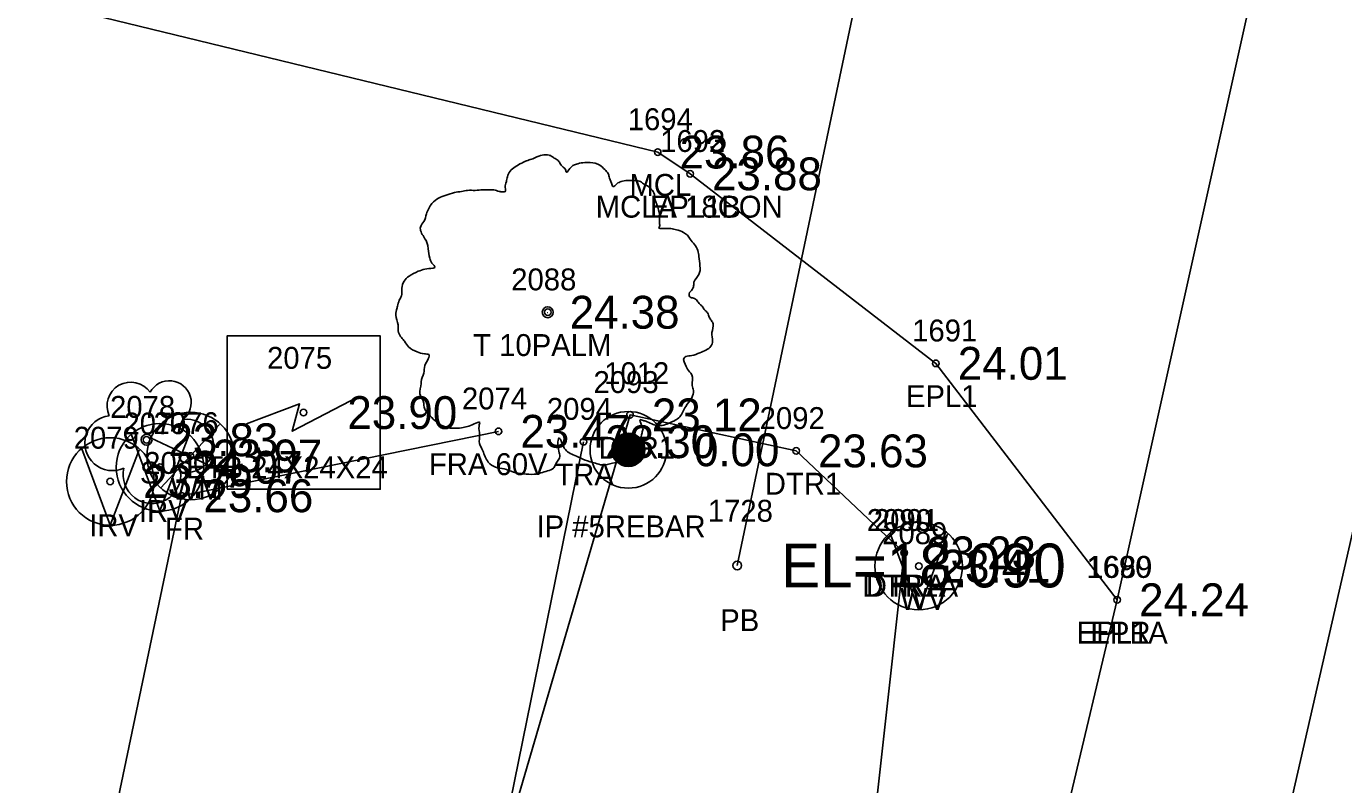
# Model space of a CAD drawing. Extents: x 2654414 to 2656963, y 761776 to 764965.
# Drawn here: x 2655410.2 to 2655470.4, y 762159.7 to 762194.4 of the extents above; entities that cross this region are included whole.
import ezdxf

# ---------------------------------------------------------------- set-up
doc = ezdxf.new("R2010")
doc.units = 0
for name, color, linetype in [('Default', 7, 'Continuous'), ('RD_EX_BldgApp', 7, 'Continuous'), ('RD_EX_Conc', 7, 'Continuous'), ('RD_EX_Conc_txCode', 7, 'Continuous'), ('RD_EX_DR_Pipe', 7, 'Continuous'), ('RD_EX_DR_Pipe_txCode', 7, 'Continuous'), ('RD_EX_DV_Prop_txCode', 7, 'Continuous'), ('RD_EX_DV_PropPin', 7, 'Continuous'), ('RD_EX_Fence_Other', 7, 'Continuous'), ('RD_EX_Fence_Other_txCode', 7, 'Continuous'), ('RD_EX_H2O', 7, 'Continuous'), ('RD_EX_H2O_txCode', 7, 'Continuous'), ('RD_EX_Misc_txCode', 7, 'Continuous'), ('RD_EX_Road', 7, 'Continuous'), ('RD_EX_Road_txCode', 7, 'Continuous'), ('RD_EX_TX_Conc_ELEV', 7, 'Continuous'), ('RD_EX_TX_DV_Prop_ELEV', 7, 'Continuous'), ('RD_EX_TX_Fence_Other_ELEV', 7, 'Continuous'), ('RD_EX_TX_H2O_ELEV', 7, 'Continuous'), ('RD_EX_TX_Misc_ELEV', 7, 'Continuous'), ('RD_EX_TX_Road_ELEV', 7, 'Continuous'), ('RD_EX_TX_UT_ELEV', 7, 'Continuous'), ('RD_EX_TX_VEG_ELEV', 7, 'Continuous'), ('RD_EX_UT', 7, 'Continuous'), ('RD_EX_UT_txCode', 7, 'Continuous'), ('RD_EX_VEG', 7, 'Continuous'), ('RD_EX_VEG_txCode', 7, 'Continuous'), ('RD_HC_Cl', 7, 'Continuous'), ('RD_SMD_Locator', 7, 'Continuous'), ('RD_TX_Pipe_ElevEX', 7, 'Continuous')]:
    doc.layers.add(name, color=color, linetype=linetype)

msp = doc.modelspace()

# ---------------------------------------------------------------- linework, layer by layer
at = {"layer": 'Default'}
msp.add_line((2656050.51, 764712.367), (2655383.263, 761787.511), dxfattribs=at)
at = {"layer": 'RD_EX_BldgApp'}
for p, q in [((2655416.316, 762172.224), (2655415.012, 762175.707)), ((2655416.316, 762172.224), (2655417.638, 762175.669)), ((2655414.044, 762171.575), (2655412.74, 762175.057)), ((2655414.044, 762171.575), (2655415.366, 762175.02))]:
    msp.add_line(p, q, dxfattribs=at)
for centre, radius in [((2655416.316, 762174.217), 2), ((2655414.044, 762173.567), 2), ((2655416.316, 762174.217), 0.15), ((2655414.044, 762173.567), 0.15)]:
    msp.add_circle(centre, radius, dxfattribs=at)
at = {"layer": 'RD_EX_Conc'}
msp.add_lwpolyline([(2655440.54, 762187.622), (2655439.059, 762188.617), (2655385.758, 762201.571), (2655364.155, 762208.612), (2655337.932, 762214.524), (2655306.963, 762222.49), (2655288.125, 762231.245)], dxfattribs=at)
at = {"layer": 'RD_EX_DR_Pipe'}
msp.add_line((2655454.649, 762226.686), (2655442.695, 762169.731), dxfattribs=at)
at = {"layer": 'RD_EX_DV_PropPin'}
for p, q in [((2655437.015, 762174.717), (2655437.015, 762175.313)), ((2655437.051, 762174.645), (2655437.051, 762175.384)), ((2655437.086, 762174.588), (2655437.086, 762175.441)), ((2655437.121, 762174.54), (2655437.121, 762175.489)), ((2655437.156, 762174.5), (2655437.156, 762175.53)), ((2655437.191, 762174.464), (2655437.191, 762175.565)), ((2655437.226, 762174.432), (2655437.226, 762175.597)), ((2655437.261, 762174.405), (2655437.261, 762175.624)), ((2655437.296, 762174.38), (2655437.296, 762175.649)), ((2655437.331, 762174.358), (2655437.331, 762175.671)), ((2655437.366, 762174.339), (2655437.366, 762175.69)), ((2655437.401, 762174.322), (2655437.401, 762175.707)), ((2655437.436, 762174.307), (2655437.436, 762175.722)), ((2655437.471, 762174.294), (2655437.471, 762175.735)), ((2655437.506, 762174.283), (2655437.506, 762175.746)), ((2655437.541, 762174.274), (2655437.541, 762175.755)), ((2655437.576, 762174.267), (2655437.576, 762175.763)), ((2655437.611, 762174.261), (2655437.611, 762175.768)), ((2655437.646, 762174.257), (2655437.646, 762175.772)), ((2655437.681, 762174.254), (2655437.681, 762175.775)), ((2655437.716, 762174.254), (2655437.716, 762175.776)), ((2655437.751, 762174.254), (2655437.751, 762175.775)), ((2655437.786, 762174.257), (2655437.786, 762175.772)), ((2655437.821, 762174.261), (2655437.821, 762175.768)), ((2655437.856, 762174.267), (2655437.856, 762175.763)), ((2655437.891, 762174.274), (2655437.891, 762175.755)), ((2655437.926, 762174.283), (2655437.926, 762175.746)), ((2655437.961, 762174.294), (2655437.961, 762175.735)), ((2655437.996, 762174.307), (2655437.996, 762175.722)), ((2655438.031, 762174.322), (2655438.031, 762175.707)), ((2655438.066, 762174.339), (2655438.066, 762175.69)), ((2655438.101, 762174.358), (2655438.101, 762175.671)), ((2655438.136, 762174.38), (2655438.136, 762175.649)), ((2655438.171, 762174.405), (2655438.171, 762175.624)), ((2655438.206, 762174.432), (2655438.206, 762175.597)), ((2655438.241, 762174.464), (2655438.241, 762175.565)), ((2655438.276, 762174.5), (2655438.276, 762175.53)), ((2655438.311, 762174.54), (2655438.311, 762175.489)), ((2655438.346, 762174.588), (2655438.346, 762175.441)), ((2655438.381, 762174.645), (2655438.381, 762175.384)), ((2655438.416, 762174.717), (2655438.416, 762175.313)), ((2655436.98, 762174.818), (2655436.98, 762175.211)), ((2655438.451, 762174.818), (2655438.451, 762175.211))]:
    msp.add_line(p, q, dxfattribs=at)
for radius in [1.75, 0.761]:
    msp.add_circle((2655437.716, 762175.015), radius, dxfattribs=at)
at = {"layer": 'RD_EX_Fence_Other'}
msp.add_lwpolyline([(2655431.783, 762175.859), (2655417.301, 762172.915), (2655393.276, 762058.242), (2655393.276, 762058.242), (2655337.575, 762053.755), (2655251.713, 762069.623), (2655221.445, 762090.342)], dxfattribs=at)
at = {"layer": 'RD_EX_H2O'}
for points in [[(2655450.323, 762170.307), (2655445.386, 762174.965), (2655437.793, 762176.609), (2655429.861, 762149.526), (2655410.493, 762053.38), (2655410.349, 762043.627), (2655388.946, 762049.63)], [(2655450.323, 762170.307), (2655447.514, 762145.047), (2655428.435, 762061.315), (2655427.047, 762050.545), (2655425.43, 762042.761), (2655423.628, 762041.006), (2655404.092, 761950.813), (2655382.096, 761859.047), (2655367.493, 761795.823)]]:
    msp.add_lwpolyline(points, dxfattribs=at)
at = {"layer": 'RD_EX_Road'}
for points in [[(2655700.994, 763232.279), (2655693.552, 763198.573), (2655671.649, 763102.037), (2655649.038, 763001.061), (2655627.271, 762906.233), (2655604.996, 762809.365), (2655598.992, 762783.09), (2655583.655, 762714.137), (2655561.97, 762618.323), (2655556.356, 762593.843), (2655548.114, 762557.141), (2655540.102, 762522.478), (2655518.03, 762425.04), (2655496.479, 762329.558), (2655475.552, 762236.625), (2655473.199, 762226.142), (2655466.574, 762197.504), (2655460.058, 762168.164), (2655454.261, 762143.776), (2655432.5, 762049.878), (2655410.7, 761955.515), (2655388.166, 761858.426), (2655373.501, 761793.951)], [(2655460.058, 762168.164), (2655451.771, 762178.965), (2655440.54, 762187.622)]]:
    msp.add_lwpolyline(points, dxfattribs=at)
at = {"layer": 'RD_EX_UT'}
for p, q in [((2655416.361, 762173.274), (2655419.028, 762176.171)), ((2655415.879, 762175.569), (2655419.51, 762173.857)), ((2655450.986, 762167.71), (2655449.682, 762171.192)), ((2655450.986, 762167.71), (2655452.308, 762171.155))]:
    msp.add_line(p, q, dxfattribs=at)
msp.add_lwpolyline([(2655419.378, 762173.215), (2655419.378, 762180.215), (2655426.378, 762180.215), (2655426.378, 762173.215)], close=True, dxfattribs=at)
msp.add_lwpolyline([(2655420.276, 762176.209), (2655422.698, 762177.109), (2655422.352, 762175.863), (2655425.397, 762177.456)], dxfattribs=at)
for centre in [(2655417.713, 762174.732), (2655450.986, 762169.703)]:
    msp.add_circle(centre, 2, dxfattribs=at)
at = {"layer": 'RD_EX_VEG'}
msp.add_lwpolyline([(2655435.663, 762175.385), (2655407.476, 762036.838), (2655372.675, 761884.87)], dxfattribs=at)
for centre, radius in [((2655434.036, 762181.3), 0.25), ((2655434.023, 762181.281), 0.0001), ((2655415.703, 762175.475), 0.25)]:
    msp.add_circle(centre, radius, dxfattribs=at)
for centre, radius, start, end in [((2655414.982, 762177.022), 1.084, 34.97629, 204.75602), ((2655416.748, 762177.177), 0.995, 308.76261, 152.04674), ((2655414.139, 762175.32), 1.257, 96.45179, 294.73401), ((2655417.543, 762175.196), 1.218, 256.56668, 98.10463), ((2655415.949, 762173.879), 1.318, 166.88266, 5.75893)]:
    msp.add_arc(centre, radius, start, end, dxfattribs=at)
for points in [[(2655434.168, 762188.467), (2655433.868, 762188.492), (2655433.543, 762188.392), (2655433.293, 762188.292), (2655433.068, 762188.217), (2655432.843, 762188.117), (2655432.543, 762187.942), (2655432.318, 762187.742), (2655432.193, 762187.493), (2655432.143, 762187.268), (2655432.093, 762186.993), (2655432.093, 762186.818), (2655431.969, 762186.793), (2655431.819, 762186.818), (2655431.569, 762186.893), (2655431.319, 762186.893), (2655431.069, 762186.893), (2655430.719, 762186.868), (2655430.369, 762186.868), (2655430.094, 762186.818), (2655429.769, 762186.768), (2655429.395, 762186.643), (2655429.045, 762186.518), (2655428.745, 762186.268), (2655428.495, 762185.793), (2655428.37, 762185.443), (2655428.22, 762185.194), (2655428.37, 762184.744), (2655428.545, 762184.394), (2655428.57, 762184.194), (2655428.645, 762183.769), (2655428.745, 762183.544), (2655428.87, 762183.344), (2655428.795, 762183.319), (2655428.42, 762183.269), (2655428.12, 762183.169), (2655427.695, 762182.945), (2655427.47, 762182.72), (2655427.37, 762182.395), (2655427.346, 762182.045), (2655427.246, 762181.845), (2655427.171, 762181.57), (2655427.146, 762181.495), (2655427.096, 762181.17), (2655427.196, 762180.72), (2655427.221, 762180.371), (2655427.346, 762180.146), (2655427.495, 762179.971), (2655427.67, 762179.721), (2655428.07, 762179.496), (2655428.395, 762179.396), (2655428.595, 762179.371), (2655428.42, 762178.871), (2655428.37, 762178.521), (2655428.245, 762178.122), (2655428.245, 762178.047), (2655428.195, 762177.572), (2655428.345, 762177.247), (2655428.42, 762176.872), (2655428.595, 762176.647), (2655428.87, 762176.347), (2655429.195, 762176.123), (2655429.695, 762175.998), (2655430.094, 762176.023), (2655430.669, 762176.197), (2655430.919, 762176.272), (2655430.894, 762176.098), (2655430.919, 762175.723), (2655430.919, 762175.298), (2655431.069, 762174.973), (2655431.169, 762174.698), (2655431.319, 762174.448), (2655431.644, 762174.223), (2655432.043, 762174.148), (2655432.468, 762173.998), (2655432.918, 762173.923), (2655433.418, 762173.898), (2655434.018, 762174.048), (2655434.292, 762174.173), (2655434.392, 762174.348), (2655434.592, 762174.723), (2655434.542, 762174.948), (2655434.567, 762175.548), (2655434.667, 762175.373), (2655434.842, 762175.023), (2655435.342, 762174.723), (2655435.742, 762174.548), (2655436.217, 762174.398), (2655436.517, 762174.323), (2655436.991, 762174.398), (2655437.366, 762174.473), (2655437.741, 762174.598), (2655438.041, 762174.873), (2655438.216, 762175.148), (2655438.266, 762175.423), (2655438.341, 762175.798), (2655438.391, 762175.973)], [(2655438.391, 762175.973), (2655438.316, 762176.148), (2655438.266, 762176.397), (2655438.341, 762176.372), (2655438.516, 762176.322), (2655438.791, 762176.197), (2655439.015, 762176.123), (2655439.34, 762176.148), (2655439.615, 762176.247), (2655440.065, 762176.522), (2655440.34, 762176.997), (2655440.615, 762177.397), (2655440.69, 762177.722), (2655440.64, 762177.947), (2655440.615, 762178.446), (2655440.415, 762178.696), (2655440.365, 762178.821), (2655440.265, 762179.221), (2655440.34, 762179.271), (2655440.615, 762179.321), (2655440.99, 762179.446), (2655441.264, 762179.571), (2655441.489, 762179.746), (2655441.564, 762179.971), (2655441.539, 762180.371), (2655441.589, 762180.77), (2655441.514, 762180.92), (2655441.414, 762181.07), (2655441.339, 762181.27), (2655441.189, 762181.42), (2655441.09, 762181.57), (2655440.99, 762181.67), (2655440.865, 762181.82), (2655440.69, 762181.945), (2655440.54, 762181.995), (2655440.49, 762182.145), (2655440.64, 762182.345), (2655440.69, 762182.445), (2655440.715, 762182.67), (2655440.94, 762183.019), (2655440.99, 762183.419), (2655440.94, 762183.844), (2655440.89, 762184.119), (2655440.74, 762184.394), (2655440.54, 762184.644), (2655440.415, 762184.819), (2655440.24, 762184.944), (2655439.915, 762185.069), (2655439.665, 762185.119), (2655439.315, 762185.119), (2655439.115, 762185.169), (2655439.14, 762185.219), (2655439.14, 762185.368), (2655439.14, 762185.643), (2655439.065, 762186.093), (2655438.915, 762186.593), (2655438.915, 762186.618), (2655438.815, 762186.868), (2655438.591, 762187.068), (2655438.416, 762187.168), (2655438.216, 762187.293), (2655437.966, 762187.318), (2655437.666, 762187.318), (2655437.391, 762187.268), (2655437.191, 762187.168), (2655437.016, 762187.043), (2655436.941, 762187.193), (2655436.841, 762187.493), (2655436.791, 762187.642), (2655436.641, 762187.817), (2655436.417, 762188.017), (2655435.967, 762188.142), (2655435.342, 762188.067), (2655435.042, 762187.867), (2655434.892, 762187.692), (2655434.842, 762187.817), (2655434.642, 762188.017), (2655434.542, 762188.192), (2655434.367, 762188.317), (2655434.218, 762188.417), (2655434.118, 762188.467)]]:
    msp.add_spline(points, degree=3, dxfattribs=at)
at = {"layer": 'RD_HC_Cl'}
msp.add_line((2656050.51, 764712.367), (2655383.263, 761787.511), dxfattribs=at)
at = {"layer": 'RD_SMD_Locator'}
for centre, radius in [((2655439.059, 762188.617), 0.15), ((2655440.54, 762187.622), 0.15), ((2655440.54, 762187.622), 0.15), ((2655434.036, 762181.3), 0.15), ((2655451.771, 762178.965), 0.15), ((2655422.878, 762176.715), 0.15), ((2655437.793, 762176.609), 0.15), ((2655431.783, 762175.859), 0.15), ((2655415.703, 762175.475), 0.15), ((2655435.663, 762175.385), 0.15), ((2655417.713, 762174.732), 0.15), ((2655437.716, 762175.015), 0.15), ((2655445.386, 762174.965), 0.15), ((2655417.301, 762172.915), 0.15), ((2655450.323, 762170.307), 0.15), ((2655450.323, 762170.307), 0.15), ((2655442.695, 762169.731), 0.2), ((2655450.986, 762169.703), 0.15), ((2655460.058, 762168.164), 0.15), ((2655460.058, 762168.164), 0.15)]:
    msp.add_circle(centre, radius, dxfattribs=at)

# ---------------------------------------------------------------- texts
at = {"layer": 'RD_EX_Conc_txCode'}
for s, p in [('1694', (2655437.689, 762189.617)), ('1693', (2655439.17, 762188.622)), ('MCL', (2655437.767, 762186.617)), ('MCLA 18CON', (2655436.225, 762185.622))]:
    msp.add_text(s, height=1, dxfattribs=at).set_placement(p)
at = {"layer": 'RD_EX_DR_Pipe_txCode'}
for s, p in [('1728', (2655441.348, 762171.731)), ('PB', (2655441.915, 762166.731))]:
    msp.add_text(s, height=1, dxfattribs=at).set_placement(p)
at = {"layer": 'RD_EX_DV_Prop_txCode'}
for s, p in [('1012', (2655436.613, 762178.015)), ('IP #5REBAR', (2655433.519, 762171.015))]:
    msp.add_text(s, height=1, dxfattribs=at).set_placement(p)
at = {"layer": 'RD_EX_Fence_Other_txCode'}
for s, p in [('2074', (2655430.113, 762176.859)), ('2080', (2655415.592, 762173.915)), ('FRA 60V', (2655428.602, 762173.859)), ('FR', (2655416.545, 762170.915))]:
    msp.add_text(s, height=1, dxfattribs=at).set_placement(p)
at = {"layer": 'RD_EX_H2O_txCode'}
for s, p in [('2093', (2655436.124, 762177.609)), ('2092', (2655443.717, 762175.965)), ('DTR1', (2655436.36, 762174.609)), ('DTR1', (2655443.953, 762172.965)), ('2090', (2655448.614, 762171.307)), ('2091', (2655448.937, 762171.307)), ('DTR1A', (2655448.401, 762168.307)), ('DTRA', (2655448.567, 762168.307))]:
    msp.add_text(s, height=1, dxfattribs=at).set_placement(p)
at = {"layer": 'RD_EX_Misc_txCode'}
for s, p in [('2077', (2655414.646, 762175.717)), ('2079', (2655412.375, 762175.067)), ('IRV', (2655415.355, 762171.717)), ('IRV', (2655413.083, 762171.067))]:
    msp.add_text(s, height=1, dxfattribs=at).set_placement(p)
at = {"layer": 'RD_EX_Road_txCode'}
for s, p in [('1692', (2655439.17, 762188.622)), ('EPL1B', (2655438.697, 762185.622)), ('1691', (2655450.685, 762179.965)), ('EPL1', (2655450.401, 762176.965)), ('1690', (2655458.648, 762169.164)), ('1689', (2655458.688, 762169.164)), ('EPL1A', (2655458.2, 762166.164)), ('EPR', (2655458.83, 762166.164))]:
    msp.add_text(s, height=1, dxfattribs=at).set_placement(p)
at = {"layer": 'RD_EX_TX_Conc_ELEV'}
for s, p in [('23.86', (2655440.059, 762187.867)), ('23.88', (2655441.54, 762186.872))]:
    msp.add_text(s, height=1.5, dxfattribs=at).set_placement(p)
at = {"layer": 'RD_EX_TX_DV_Prop_ELEV'}
msp.add_text('0.00', height=1.5, dxfattribs=at).set_placement((2655440.716, 762174.265))
at = {"layer": 'RD_EX_TX_Fence_Other_ELEV'}
for s, p in [('23.47', (2655432.783, 762175.109)), ('23.66', (2655418.301, 762172.165))]:
    msp.add_text(s, height=1.5, dxfattribs=at).set_placement(p)
at = {"layer": 'RD_EX_TX_H2O_ELEV'}
for s, p in [('23.12', (2655438.793, 762175.859)), ('23.63', (2655446.386, 762174.215)), ('23.23', (2655451.323, 762169.557)), ('23.23', (2655451.323, 762169.557))]:
    msp.add_text(s, height=1.5, dxfattribs=at).set_placement(p)
at = {"layer": 'RD_EX_TX_Misc_ELEV'}
for s, p in [('24.07', (2655417.816, 762173.467)), ('23.79', (2655415.544, 762172.817))]:
    msp.add_text(s, height=1.5, dxfattribs=at).set_placement(p)
at = {"layer": 'RD_EX_TX_Road_ELEV'}
for s, p in [('23.88', (2655441.54, 762186.872)), ('24.01', (2655452.771, 762178.215)), ('24.24', (2655461.058, 762167.414)), ('24.24', (2655461.058, 762167.414))]:
    msp.add_text(s, height=1.5, dxfattribs=at).set_placement(p)
at = {"layer": 'RD_EX_TX_UT_ELEV'}
for s, p in [('23.90', (2655424.878, 762175.965)), ('23.97', (2655418.713, 762173.982)), ('23.41', (2655451.986, 762168.953))]:
    msp.add_text(s, height=1.5, dxfattribs=at).set_placement(p)
at = {"layer": 'RD_EX_TX_VEG_ELEV'}
for s, p in [('24.38', (2655435.036, 762180.55)), ('23.83', (2655416.703, 762174.725)), ('23.30', (2655436.663, 762174.635))]:
    msp.add_text(s, height=1.5, dxfattribs=at).set_placement(p)
at = {"layer": 'RD_EX_UT_txCode'}
for s, p in [('2075', (2655421.208, 762178.715)), ('2076', (2655416.02, 762175.732)), ('ETB 24X24X24', (2655417.508, 762173.715)), ('WM', (2655416.807, 762172.732)), ('2089', (2655449.316, 762170.703)), ('WV', (2655450.127, 762167.703))]:
    msp.add_text(s, height=1, dxfattribs=at).set_placement(p)
at = {"layer": 'RD_EX_VEG_txCode'}
for s, p in [('2088', (2655432.366, 762182.3)), ('T 10PALM', (2655430.626, 762179.3)), ('2078', (2655414.034, 762176.475)), ('2094', (2655433.994, 762176.385)), ('S', (2655415.396, 762173.475)), ('TRA', (2655434.38, 762173.385))]:
    msp.add_text(s, height=1, dxfattribs=at).set_placement(p)
at = {"layer": 'RD_TX_Pipe_ElevEX'}
msp.add_text('EL=18.090', height=2, dxfattribs=at).set_placement((2655444.695, 762168.731))

doc.saveas('drawing.dxf')
